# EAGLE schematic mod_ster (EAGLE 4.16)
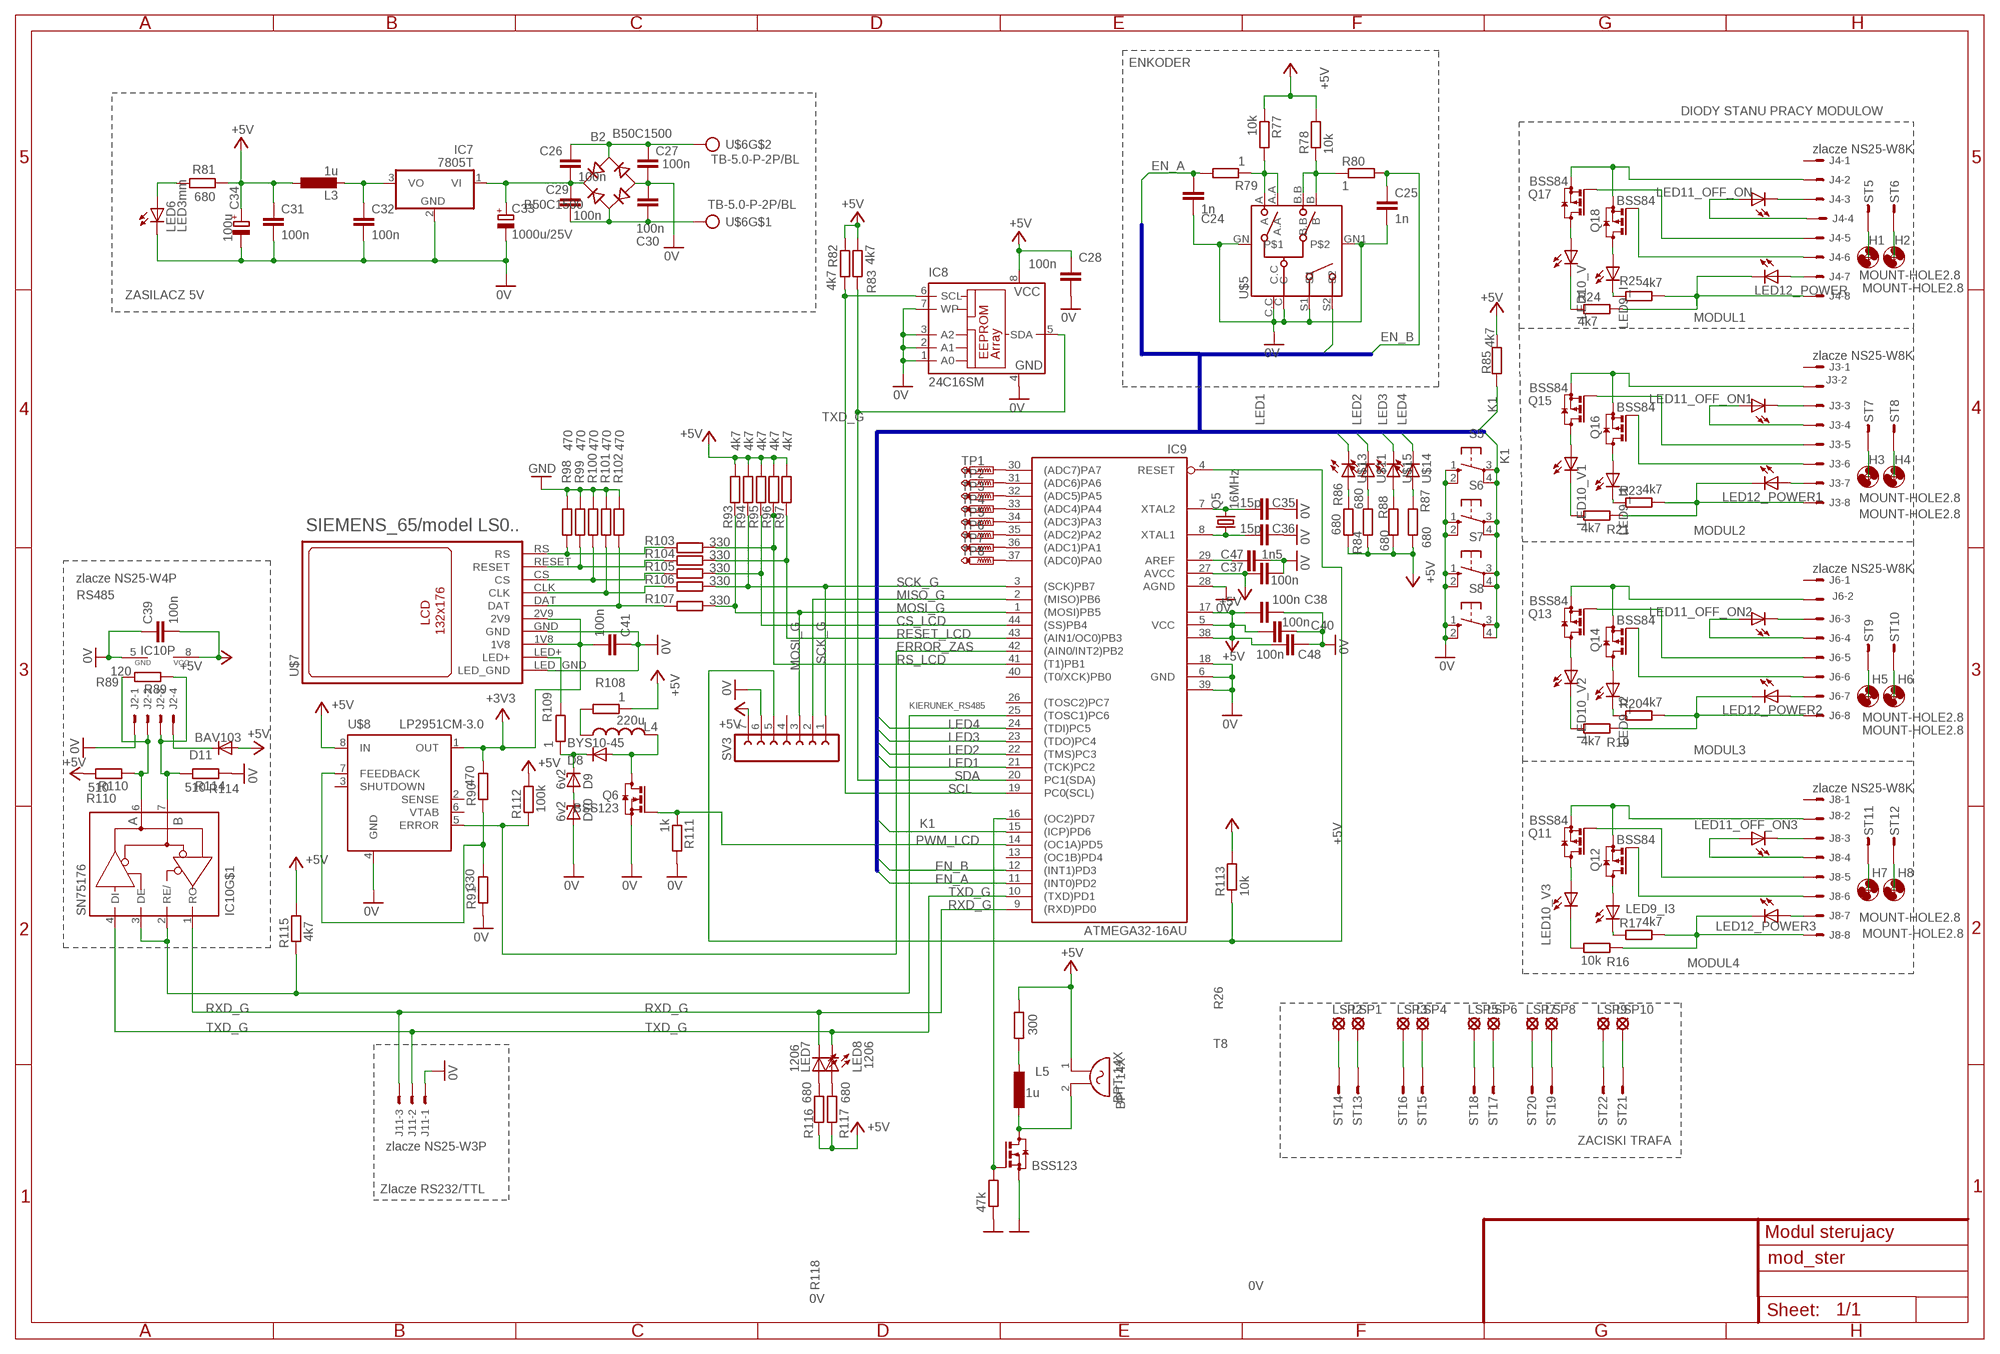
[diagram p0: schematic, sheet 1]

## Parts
B2  B50C1500  RB1A  [RB1A]
BPT-14X  BPT-14X  F/HGP  [F/HGP]
C24  1n  C-EUC0805  [C0805]
C25  1n  C-EUC0805  [C0805]
C26  100n  C-EUC1206  [C1206]
C27  100n  C-EUC1206  [C1206]
C28  100n  C-EUC0805  [C0805]
C29  100n  C-EUC1206  [C1206]
C30  100n  C-EUC1206  [C1206]
C31  100n  C-EUC0805  [C0805]
C32  100n  C-EUC0805  [C0805]
C33  1000u/25V  CPOL-EUTT5D11L  [TT5D11L]
C34  100u  CPOL-EUTT2D5L  [TT2D5L]
C35  15p  C-EUC0805K  [C0805K]
C36  15p  C-EUC0805K  [C0805K]
C37  100n  C-EUC0805K  [C0805K]
C38  100n  C-EUC0805K  [C0805K]
C39  100n  C-EUC0805  [C0805]
C40  100n  C-EUC0805K  [C0805K]
C41  100n  C-EUC0805K  [C0805K]
C47  1n5  C-EUC0805K  [C0805K]
C48  100n  C-EUC0805K  [C0805K]
D8  BYS10-45  BYS10  [SOD106A]
D9  6v2  BZX84CSMD  [TO236]
D10  6v2  BZX84CSMD  [TO236]
D11  BAV103  DIODE-MINIMELF  [MINIMELF]
H1  MOUNT-HOLE2.8  [2,8]
H2  MOUNT-HOLE2.8  [2,8]
H3  MOUNT-HOLE2.8  [2,8]
H4  MOUNT-HOLE2.8  [2,8]
H5  MOUNT-HOLE2.8  [2,8]
H6  MOUNT-HOLE2.8  [2,8]
H7  MOUNT-HOLE2.8  [2,8]
H8  MOUNT-HOLE2.8  [2,8]
IC7  7805T  [TO220H]
IC8  24C16SM  24C64SM  [SO-08M]
IC9  ATMEGA32-16AU  MEGA32-A  [TQFP44]
IC10  SN75176  MAX481CSA  [SO08]
J2  zlacze NS25-W4P  22-27-2041-04  [6410-04]
J3  zlacze NS25-W8K  22-27-2081-08  [6410-08]
J4  zlacze NS25-W8K  22-27-2081-08  [6410-08]
J6  zlacze NS25-W8K  22-27-2081-08  [6410-08]
J8  zlacze NS25-W8K  22-27-2081-08  [6410-08]
J11  zlacze NS25-W3P  22-27-2031-03  [6410-03]
L3  1u  L-EU0207/15  [0207/15@1]
L4  220u  L-US0207/12  [0207/12]
L5  1u  L-EU0207/15  [0207/15@1]
LED6  LED3mm  LED3MM  [LED3MM]
LED7  1206  LEDCHIPLED_1206  [CHIPLED_1206]
LED8  1206  LEDCHIPLED_1206  [CHIPLED_1206]
LED9_I  LED3MM  [LED3MM]
LED9_I1  LED3MM  [LED3MM]
LED9_I2  LED3MM  [LED3MM]
LED9_I3  LED3MM  [LED3MM]
LED10_V  LED3MM  [LED3MM]
LED10_V1  LED3MM  [LED3MM]
LED10_V2  LED3MM  [LED3MM]
LED10_V3  LED3MM  [LED3MM]
LED11_OFF_ON  LED3MM  [LED3MM]
LED11_OFF_ON1  LED3MM  [LED3MM]
LED11_OFF_ON2  LED3MM  [LED3MM]
LED11_OFF_ON3  LED3MM  [LED3MM]
LED12_POWER  LED3MM  [LED3MM]
LED12_POWER1  LED3MM  [LED3MM]
LED12_POWER2  LED3MM  [LED3MM]
LED12_POWER3  LED3MM  [LED3MM]
LSP1  SE14  [SE14]
LSP2  SE14  [SE14]
LSP3  SE14  [SE14]
LSP4  SE14  [SE14]
LSP5  SE14  [SE14]
LSP6  SE14  [SE14]
LSP7  SE14  [SE14]
LSP8  SE14  [SE14]
LSP9  SE14  [SE14]
LSP10  SE14  [SE14]
Q5  16MHz  CRYSTALHC49U70  [HC49U70]
Q6  BSS123  [SOT23]
Q11  BSS84  [SOT23]
Q12  BSS84  [SOT23]
Q13  BSS84  [SOT23]
Q14  BSS84  [SOT23]
Q15  BSS84  [SOT23]
Q16  BSS84  [SOT23]
Q17  BSS84  [SOT23]
Q18  BSS84  [SOT23]
R16  10k  R-EU_R0805  [R0805]
R17  4k7  R-EU_R0805  [R0805]
R19  4k7  R-EU_R0805  [R0805]
R20  4k7  R-EU_R0805  [R0805]
R21  4k7  R-EU_R0805  [R0805]
R23  4k7  R-EU_R0805  [R0805]
R24  4k7  R-EU_R0805  [R0805]
R25  4k7  R-EU_R0805  [R0805]
R26  300  R-EU_R0805  [R0805]
R77  10k  R-EU_M1206  [M1206]
R78  10k  R-EU_M1206  [M1206]
R79  1  R-EU_M1206  [M1206]
R80  1  R-EU_M1206  [M1206]
R81  680  R-EU_M0805  [M0805]
R82  4k7  R-EU_M0805  [M0805]
R83  4k7  R-EU_M0805  [M0805]
R84  680  R-EU_R0805  [R0805]
R85  4k7  R-EU_R0805  [R0805]
R86  680  R-EU_R0805  [R0805]
R87  680  R-EU_R0805  [R0805]
R88  680  R-EU_R0805  [R0805]
R89  120  R-EU_R0805  [R0805]
R90  470  R-EU_R0805  [R0805]
R91  330  R-EU_R0805  [R0805]
R93  4k7  R-EU_R0805  [R0805]
R94  4k7  R-EU_R0805  [R0805]
R95  4k7  R-EU_R0805  [R0805]
R96  4k7  R-EU_R0805  [R0805]
R97  4k7  R-EU_R0805  [R0805]
R98  470  R-EU_R0805  [R0805]
R99  470  R-EU_R0805  [R0805]
R100  470  R-EU_R0805  [R0805]
R101  470  R-EU_R0805  [R0805]
R102  470  R-EU_R0805  [R0805]
R103  330  R-EU_R0805  [R0805]
R104  330  R-EU_R0805  [R0805]
R105  330  R-EU_R0805  [R0805]
R106  330  R-EU_R0805  [R0805]
R107  330  R-EU_R0805  [R0805]
R108  1  R-EU_R0805  [R0805]
R109  1  R-EU_R0805  [R0805]
R110  510  R-EU_R0805  [R0805]
R111  1k  R-EU_R0805  [R0805]
R112  100k  R-EU_R0805  [R0805]
R113  10k  R-EU_M0805  [M0805]
R114  510  R-EU_R0805  [R0805]
R115  4k7  R-EU_M0805  [M0805]
R116  680  R-EU_M0805  [M0805]
R117  680  R-EU_M0805  [M0805]
R118  47k  R-EU_R0805  [R0805]
S5  10-XX  [B3F-10XX]
S6  10-XX  [B3F-10XX]
S7  10-XX  [B3F-10XX]
S8  10-XX  [B3F-10XX]
ST5  ST2,8  [ST2,8]
ST6  ST2,8  [ST2,8]
ST7  ST2,8  [ST2,8]
ST8  ST2,8  [ST2,8]
ST9  ST2,8  [ST2,8]
ST10  ST2,8  [ST2,8]
ST11  ST2,8  [ST2,8]
ST12  ST2,8  [ST2,8]
ST13  ST2,8  [ST2,8]
ST14  ST2,8  [ST2,8]
ST15  ST2,8  [ST2,8]
ST16  ST2,8  [ST2,8]
ST17  ST2,8  [ST2,8]
ST18  ST2,8  [ST2,8]
ST19  ST2,8  [ST2,8]
ST20  ST2,8  [ST2,8]
ST21  ST2,8  [ST2,8]
ST22  ST2,8  [ST2,8]
SV3  FE07-1  [FE07]
T8  BSS123  [SOT23]
TP1  PTR1B1,27  [B1,27]
TP2  PTR1B1,27  [B1,27]
TP3  PTR1B1,27  [B1,27]
TP4  PTR1B1,27  [B1,27]
TP5  PTR1B1,27  [B1,27]
TP6  PTR1B1,27  [B1,27]
TP7  PTR1B1,27  [B1,27]
TP8  PTR1B1,27  [B1,27]
U$5  ED16112O  [ENKODER_PROSTY]
U$6  TB-5.0-P-2P/BL  AK300/2_MK  [AK300/2_MK]
U$7  SIEMENS_65/model LS0..  SIEMENS_65  [SIEMENS65]
U$8  LP2951CM-3.0  LM2951  [SO08]
U$11  LED3MM  [LED3MM]
U$13  LED3MM  [LED3MM]
U$14  LED3MM  [LED3MM]
U$15  LED3MM  [LED3MM]

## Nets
0V: B2.- C24.2 C25.2 C27.2 C28.2 C30.1 C31.2 C32.2 C33.- C34.- C35.1 C36.1 C37.2 C38.1 C39.1 C40.1 C41.1 C47.2 C48.1 D10.A IC7.2(GND) IC8.1(A0) IC8.2(A1) IC8.3(A2) IC8.4(GND) IC8.7(WP) IC9.6(GND) IC9.18(GND1) IC9.28(AGND) IC9.39(GND2) IC10.5(P:GND) J2.1 J11.1 LED6.K(C) Q6.2(S) R91.1 R98.2 R99.2 R100.2 R101.2 R102.2 R111.2 R114.1 R118.1 S5.1(S) S5.2(S1) S6.1(S) S6.2(S1) S7.1(S) S7.2(S1) S8.1(S) S8.2(S1) SV3.6 T8.2(S) U$5.C U$5.C.C U$5.GN U$5.GN1 U$5.S1 U$7.GND U$7.LED_GND U$8.4(GND) ; supply symbol labelled GND
+3V3: C41.2 R90.2 U$7.1V8 U$7.2V9 U$8.1(OUT)
+5V: BPT-14X.1 C28.1 C31.1 C34.+ C37.1 C38.2 C39.2 C40.2 C48.2 D11.A IC8.8(VCC) IC9.5(VCC) IC9.17(VCC1) IC9.27(AVCC) IC9.38(VCC2) IC10.8(P:VCC) L3.1 R26.2 R77.1 R78.2 R81.1 R82.1 R83.1 R84.1 R85.1 R86.1 R87.1 R88.1 R93.2 R94.2 R95.2 R96.2 R97.2 R108.1 R110.2 R112.2 R113.2 R115.2 R116.1 R117.1 SV3.7 U$8.8(IN)
+_1: ST5.1(ST)
+_2: ST7.1(ST)
+_3: ST9.1(ST)
+_4: ST11.1(ST)
+_5: LSP1.MP ST13.1(ST)
+_6: LSP4.MP ST15.1(ST)
+_7: LSP6.MP ST17.1(ST)
+_8: LSP8.MP ST19.1(ST)
+_9: LSP10.MP ST21.1(ST)
-_1: ST6.1(ST)
-_2: ST8.1(ST)
-_3: ST10.1(ST)
-_4: ST12.1(ST)
-_5: LSP2.MP ST14.1(ST)
-_6: LSP3.MP ST16.1(ST)
-_7: LSP5.MP ST18.1(ST)
-_8: LSP7.MP ST20.1(ST)
-_9: LSP9.MP ST22.1(ST)
A_S: IC10.6(A) J2.2 R89.2 R110.1
B_S: IC10.7(B) J2.3 R89.1 R114.2
CS_LCD: IC9.44((SS)PB4) R95.1 R105.2
EN_A: C24.1 IC9.11((INT0)PD2) R79.2
EN_B: C25.1 IC9.12((INT1)PD3) R80.2
ERROR_ZAS: IC9.42((AIN0/INT2)PB2) R112.1 U$8.5(ERROR)
GND_M: J8.8 LED12_POWER3.K(C) R16.2 R17.2
GND_M1: J6.8 LED12_POWER2.K(C) R19.2 R20.2
GND_M2: J3.8 LED12_POWER1.K(C) R21.2 R23.2
GND_M3: J4.8 LED12_POWER.K(C) R24.2 R25.2
K1: IC9.15((ICP)PD6) R85.2 S5.3(P) S5.4(P1) S6.3(P) S6.4(P1) S7.3(P) S7.4(P1) S8.3(P) S8.4(P1) U$5.S2
KIERUNEK_RS485: IC9.25((TOSC1)PC6) IC10.2(RE/) IC10.3(DE) R115.1
LED1: IC9.21((TCK)PC2) U$13.K(C)
LED2: IC9.22((TMS)PC3) U$11.K(C)
LED3: IC9.23((TDO)PC4) U$15.K(C)
LED4: IC9.24((TDI)PC5) U$14.K(C)
MISO_G: IC9.2((MISO)PB6) SV3.2
MOSI_G: IC9.1((MOSI)PB5) R93.1 R107.2 SV3.3
N$9: LED10_V.K(C) R24.1
N$13: IC9.30((ADC7)PA7) TP1.PP(TP)
N$15: IC9.31((ADC6)PA6) TP2.PP(TP)
N$18: IC9.32((ADC5)PA5) TP3.PP(TP)
N$20: LED9_I.K(C) R25.1
N$21: D11.C J2.4
N$24: LED9_I.A Q18.3(D)
N$26: IC9.33((ADC4)PA4) TP4.PP(TP)
N$27: IC9.34((ADC3)PA3) TP5.PP(TP)
N$29: IC9.35((ADC2)PA2) TP6.PP(TP)
N$30: IC9.36((ADC1)PA1) TP7.PP(TP)
N$32: IC9.37((ADC0)PA0) TP8.PP(TP)
N$46: J4.7 LED12_POWER.A
N$53: J4.6 Q18.1(G)
N$58: C47.1 IC9.29(AREF)
N$70: J4.3 LED11_OFF_ON.K(C)
N$71: J4.4 LED11_OFF_ON.A
N$72: LED10_V1.A Q15.3(D)
N$73: LED10_V1.K(C) R21.1
N$74: LED9_I1.K(C) R23.1
N$75: J3.7 LED12_POWER1.A
N$76: LED9_I1.A Q16.3(D)
N$77: J3.3 LED11_OFF_ON1.K(C)
N$78: J3.4 LED11_OFF_ON1.A
N$79: R98.1 R103.1 U$7.RS
N$80: C35.2 IC9.7(XTAL2) Q5.2
N$81: LED10_V2.A Q13.3(D)
N$82: LED10_V2.K(C) R19.1
N$83: LED9_I2.K(C) R20.1
N$84: J6.7 LED12_POWER2.A
N$85: C36.2 IC9.8(XTAL1) Q5.1
N$86: LED7.A R116.2
N$87: LED8.A R117.2
N$89: R84.2 U$11.A
N$90: R100.1 R105.1 U$7.CS
N$91: R101.1 R106.1 U$7.CLK
N$92: R86.2 U$13.A
N$93: R109.2 U$7.LED+
N$94: R90.1 R91.2 U$8.7(FEEDBACK)
N$95: C32.1 IC7.3(VO) L3.2
N$96: LED6.A R81.2
N$97: B2.AC2 C29.2 C30.2 U$6.1
N$101: LED9_I2.A Q14.3(D)
N$103: J6.3 LED11_OFF_ON2.K(C)
N$104: R87.2 U$14.A
N$105: D8.A L4.2 Q6.3(D)
N$106: D9.A D10.C
N$107: D8.K D9.C R109.1
N$108: L4.1 R108.2
N$109: B2.AC1 C26.1 C27.1 U$6.2
N$110: B2.+ C26.2 C29.1 C33.+ IC7.1(VI)
N$111: R99.1 R104.1 U$7.RESET
N$113: R102.1 R107.1 U$7.DAT
N$114: J6.4 LED11_OFF_ON2.A
N$116: LED9_I3.K(C) R17.1
N$117: LED9_I3.A Q12.3(D)
N$118: J8.6 Q12.1(G)
N$119: J8.7 LED12_POWER3.A
N$120: R88.2 U$15.A
N$121: J8.5 Q11.1(G)
N$122: J8.3 LED11_OFF_ON3.K(C)
N$123: J8.4 LED11_OFF_ON3.A
N$125: L5.2 R26.1
N$129: J8.2 Q11.2(S) Q12.2(S)
N$130: BPT-14X.2 L5.1 T8.3(D)
N$131: LED10_V3.A Q11.3(D)
N$132: LED10_V3.K(C) R16.1
N$133: J6.6 Q14.1(G)
N$134: J6.5 Q13.1(G)
N$135: J6.2 Q13.2(S) Q14.2(S)
N$136: J3.6 Q16.1(G)
N$137: J3.5 Q15.1(G)
N$138: J3.2 Q15.2(S) Q16.2(S)
N$139: J4.5 Q17.1(G)
N$140: J4.2 Q17.2(S) Q18.2(S)
N$141: LED10_V.A Q17.3(D)
N$151: R77.2 R79.1 U$5.A U$5.A.A
N$152: R78.1 R80.1 U$5.B U$5.B.B
PIK: IC9.16((OC2)PD7) R118.2 T8.1(G)
PWM_LCD: IC9.14((OC1A)PD5) Q6.1(G) R111.1
RESET_LCD: IC9.43((AIN1/OC0)PB3) R97.1 R104.2
RS_LCD: IC9.41((T1)PB1) R96.1 R103.2
RST_G: IC9.4(RESET) R113.1 SV3.5
RXD_G: IC9.9((RXD)PD0) IC10.1(RO) J11.3 LED7.C
SCK_G: IC9.3((SCK)PB7) R94.1 R106.2 SV3.1
SCL: IC8.6(SCL) IC9.19(PC0(SCL)) R82.2
SDA: IC8.5(SDA) IC9.20(PC1(SDA)) R83.2
TXD_G: IC9.10((TXD)PD1) IC10.4(DI) J11.2 LED8.C
Unconnected: IC9.13((OC1B)PD4) IC9.26((TOSC2)PC7) IC9.40((T0/XCK)PB0) J3.1 J4.1 J6.1 J8.1 SV3.4 U$8.2(SENSE) U$8.6(VTAB)

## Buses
K1,K2,K3,K4,K5,K6,K7,K8,EN_A,EN_B,LED1,LED2,LED3,LED4

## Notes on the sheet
- ENKODER
- DIODY STANU PRACY MODULOW
- B50C1500
- ZASILACZ 5V
- MODUL1
- SIEMENS_65/model LS0.. | MODUL2
- RS485
- R89
- MODUL3
- R114
- R110
- MODUL4
- ZACISKI TRAFA
- Zlacze RS232/TTL
- Modul sterujacy

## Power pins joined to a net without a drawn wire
SHUTDOWN: U$8.3(SHUTDOWN)

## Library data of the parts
B2 = rectifier:RB1A: RECTIFIER 1 A
BPT-14X = buzzer:F/HGP: BUZZER
C24-C32 C35-C41 C47 C48 = rcl:C-EU: CAPACITOR, European symbol
C33 C34 = rcl:CPOL-EU: POLARIZED CAPACITOR, European symbol
D8 = telefunken:BYS10: DIODE
D9 D10 = diode:BZX84CSMD: Z DIODE
D11 = diode:DIODE-: DIODE
H1-H8 = holes:MOUNT-HOLE: MOUNTING HOLE with drill center marker
IC7 = linear:78*: Positive VOLTAGE REGULATOR Source: http://cache.national.com/ds/LM/LM78L05.pdf http://www.fairchildsemi.com/ds/LM/LM7805.pdf
IC8 = microchip:24*: Serial EEPROM I2C
IC9 = atmel:MEGA32: MICROCONTROLLER 32 Kbytes FLASH 2 Kbytes SRAM 1 Kbytes EEPROM USART 8-channel 10 bit ADC Source: www.atmel.com .. doc2503.pdf
IC10 = maxim:MAX481CSA: RS485 TRANSEIVER
J2 = con-molex:22-?-04: CONNECTOR wire to board 2.54 mm (.1 inch) pitch header
J3 J4 J6 J8 = con-molex:22-?-08: CONNECTOR wire to board 2.54 mm (.1 inch) pitch header
J11 = con-molex:22-?-03: CONNECTOR wire to board 2.54 mm (.1 inch) pitch header
L3 L5 = rcl:L-EU: INDUCTOR, European symbol
L4 = rcl:L-US: INDUCTOR, American symbol
LED6-LED8 LED9_I LED9_I1-LED9_I3 LED10_V LED10_V1-LED10_V3 LED11_OFF_ON LED11_OFF_ON1-LED11_OFF_ON3 LED12_POWER LED12_POWER1-LED12_POWER3 U$11 U$13-U$15 = led:LED: LED
LSP1-LSP10 = solpad:SE14: SOLDER PAD
Q5 = crystal:CRYSTAL: CRYSTAL
Q6 T8 = transistor-small-signal:BSS123: N-CHANNEL MOS FET
Q11-Q18 = transistor-small-signal:BSS84: P-CHANNEL MOS FET
R16 R17 R19-R21 R23-R26 R77-R91 R93-R118 = rcl:R-EU_: RESISTOR, European symbol
S5-S8 = switch-omron:10-XX: OMRON SWITCH
ST5-ST22 = con-rib:ST2,8: RIBBON CABLE CONNECTOR
SV3 = con-lsta:FE07-1: FEMALE HEADER
TP1-TP8 = testpad:PTR1: TEST PIN
U$5 = piher:ED16112O
U$6 = con-ptr500:AK300/2_MK
U$7 = display-lcd:SIEMENS_65
U$8 = linear:LM2951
